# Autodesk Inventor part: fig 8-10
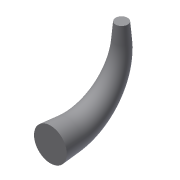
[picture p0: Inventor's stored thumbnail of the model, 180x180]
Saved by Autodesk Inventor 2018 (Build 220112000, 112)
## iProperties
Shininess: 77.0
Length Units: 11269
Angle Units: 11279
Time Units: 11290
Mass Units: 11283
Length Display Precision: 3
Angle Display Precision: 2
Created: 2001-12
Part Number: fig 8-10
Document SubType Name: Modeling
Designer: CADSoft
Density: 1 g/cm^3
Material: Generic
Appearance: Default
Density: 0.0
Volumn: 0.0
Area: 0.0
PropertySet Name: Model Information
Control State: 0
Master: False
Checked Out: False
Author: CADSoft
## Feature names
1. Sweep7
## Parameters: d4 = 15 mm, d5 = 15 mm, d13 = -5 deg, d14 = 0
